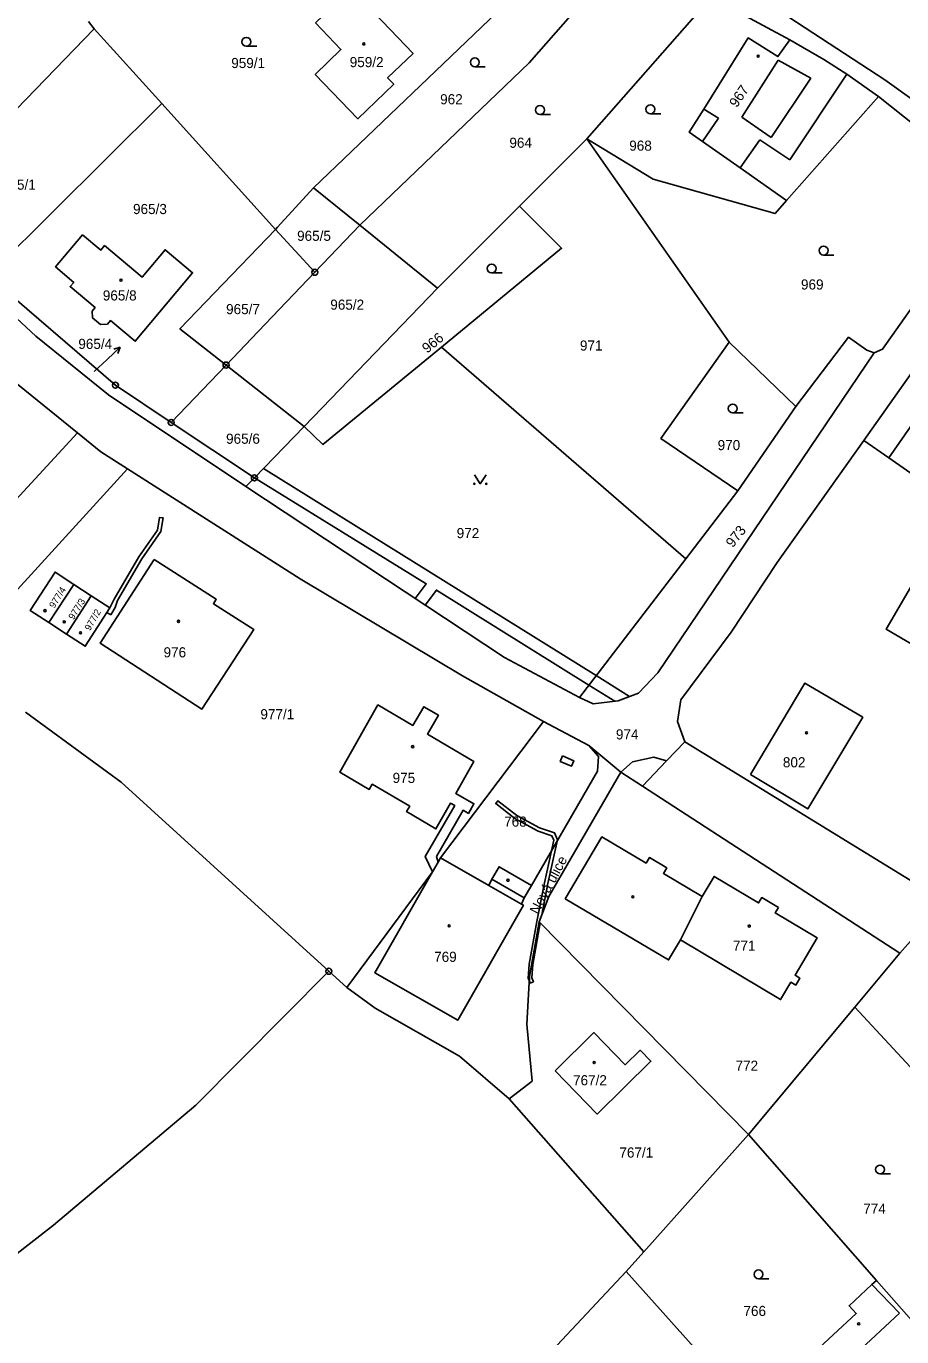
# Model space of a CAD drawing. Extents: x -504988 to -494607, y -1123820 to -1114018.
# Drawn here: x -497545.8 to -497398.6, y -1120433.9 to -1120213.7 of the extents above; entities that cross this region are included whole.
import ezdxf

# ---------------------------------------------------------------- set-up
doc = ezdxf.new("R2010")
doc.units = 0
for name, color, linetype in [('Hranice parcel', 7, 'Continuous'), ('Parcelní čísla', 7, 'Continuous'), ('Pop  PČ popisy', 7, 'Continuous'), ('Vnitřní kresba', 7, 'Continuous'), ('Věcná břemena k části', 7, 'Continuous'), ('Značky bodu BP', 7, 'Continuous'), ('Značky budov', 7, 'Continuous'), ('Značky kultur', 7, 'Continuous')]:
    doc.layers.add(name, color=color, linetype=linetype)

msp = doc.modelspace()

# ---------------------------------------------------------------- linework, layer by layer
at = {"layer": 'Hranice parcel'}
for p, q in [((-497465.37, -1120210.16), (-497497.45, -1120240.87)), ((-497430.82, -1120208.74), (-497417.41, -1120215.98)), ((-497534.33, -1120214.13), (-497535.29, -1120212.91)), ((-497563.92, -1120244.66), (-497534.33, -1120214.13)), ((-497522.97, -1120226.7), (-497534.33, -1120214.13)), ((-497417.92, -1120243), (-497402.47, -1120225.5)), ((-497552.14, -1120255.64), (-497522.97, -1120226.7)), ((-497503.85, -1120247.86), (-497522.97, -1120226.7)), ((-497462.83, -1120243.96), (-497451.51, -1120232.65)), ((-497451.51, -1120232.65), (-497427.61, -1120266.81)), ((-497497.45, -1120240.87), (-497489.7, -1120247.16)), ((-497476.62, -1120257.73), (-497462.83, -1120243.96)), ((-497514.12, -1120258.51), (-497503.85, -1120247.86)), ((-497503.85, -1120247.86), (-497497.25, -1120255.06)), ((-497489.7, -1120247.16), (-497497.25, -1120255.06)), ((-497489.7, -1120247.16), (-497476.62, -1120257.73)), ((-497499.05, -1120280.96), (-497476.62, -1120257.73)), ((-497475.95, -1120267.63), (-497434.88, -1120303.23)), ((-497427.61, -1120266.81), (-497416.37, -1120277.6)), ((-497521.38, -1120280.29), (-497512.16, -1120270.65)), ((-497512.16, -1120270.65), (-497499.05, -1120280.96)), ((-497400.74, -1120286.25), (-497393.19, -1120275.35)), ((-497426.11, -1120291.8), (-497416.37, -1120277.6)), ((-497507.4, -1120289.61), (-497521.38, -1120280.29)), ((-497499.05, -1120280.96), (-497507.4, -1120289.61)), ((-497537.13, -1120282.05), (-497566.22, -1120313.52)), ((-497400.74, -1120286.25), (-497404.97, -1120283.3)), ((-497557.94, -1120320.1), (-497528.73, -1120288.08)), ((-497508.81, -1120291.07), (-497507.4, -1120289.61)), ((-497434.88, -1120303.23), (-497426.11, -1120291.8)), ((-497452.76, -1120326.51), (-497434.88, -1120303.23)), ((-497537.76, -1120307.5), (-497541.94, -1120313.93)), ((-497537.76, -1120307.5), (-497534.82, -1120309.41)), ((-497534.82, -1120309.41), (-497538.99, -1120315.85)), ((-497538.99, -1120315.85), (-497541.94, -1120313.93)), ((-497458.82, -1120330.56), (-497476.11, -1120353.44)), ((-497445.81, -1120339.06), (-497442.15, -1120341.44)), ((-497442.15, -1120341.44), (-497398.87, -1120369.47)), ((-497476.11, -1120353.44), (-497476.53, -1120354.18)), ((-497477.45, -1120355.79), (-497491.87, -1120375.25)), ((-497476.53, -1120354.18), (-497477.45, -1120355.79)), ((-497459.54, -1120364.2), (-497424.35, -1120399.95)), ((-497398.87, -1120369.47), (-497395.34, -1120365.5)), ((-497406.47, -1120378.57), (-497398.87, -1120369.47)), ((-497491.87, -1120375.25), (-497494.88, -1120372.52)), ((-497424.35, -1120399.95), (-497406.47, -1120378.57)), ((-497381.93, -1120405.05), (-497406.47, -1120378.57)), ((-497441.91, -1120419.64), (-497464.56, -1120393.93)), ((-497424.35, -1120399.95), (-497441.91, -1120419.64)), ((-497402.82, -1120424.48), (-497424.35, -1120399.95)), ((-497441.91, -1120419.64), (-497444.89, -1120422.98)), ((-497444.89, -1120422.98), (-497466.63, -1120446.14)), ((-497422.13, -1120448.35), (-497444.89, -1120422.98)), ((-497383.69, -1120446.26), (-497402.82, -1120424.48))]:
    msp.add_line(p, q, dxfattribs=at)
for points in [[(-497434.54, -1120200.6), (-497429.66, -1120204.25), (-497401.43, -1120222.74), (-497391.53, -1120229.8), (-497382.81, -1120241.08)], [(-497489.7, -1120247.16), (-497461.23, -1120219.88), (-497446.5, -1120203.09)], [(-497497.14, -1120213.13), (-497491.11, -1120207.39), (-497480.72, -1120218.27), (-497485.01, -1120222.38), (-497483.97, -1120223.46), (-497490.02, -1120229.25), (-497497.16, -1120221.8), (-497492.84, -1120217.64), (-497497.14, -1120213.13)], [(-497451.51, -1120232.65), (-497431.41, -1120209.76), (-497430.82, -1120208.74)], [(-497417.41, -1120215.98), (-497419.39, -1120218.82), (-497424.36, -1120215.69), (-497431.84, -1120227.63), (-497434.29, -1120231.53), (-497432.08, -1120233.08), (-497425.76, -1120237.51), (-497417.92, -1120243)], [(-497417.41, -1120215.98), (-497411.68, -1120219.31), (-497407.82, -1120221.79), (-497402.47, -1120225.5)], [(-497402.47, -1120225.5), (-497393.75, -1120232.44), (-497385.34, -1120244.67)], [(-497451.51, -1120232.65), (-497440.34, -1120239.4), (-497419.86, -1120245.2), (-497417.92, -1120243)], [(-497371.73, -1120236.29), (-497376.09, -1120242.49), (-497404.97, -1120283.3)], [(-497497.45, -1120240.87), (-497503.53, -1120247.5), (-497503.85, -1120247.86)], [(-497475.95, -1120267.63), (-497455.76, -1120251.03), (-497462.83, -1120243.96)], [(-497385.34, -1120244.67), (-497401.79, -1120267.99), (-497403.21, -1120268.62)], [(-497508.81, -1120291.07), (-497531.94, -1120275.65), (-497544.12, -1120265.81), (-497565.3, -1120246.14)], [(-497532.1, -1120263.76), (-497533.27, -1120263.86), (-497534.6, -1120262.72), (-497534.67, -1120261.58), (-497534.18, -1120261), (-497538.39, -1120257.47), (-497537.77, -1120256.77), (-497540.83, -1120254.12), (-497536.29, -1120248.78), (-497533.21, -1120251.33), (-497532.58, -1120250.57), (-497526.25, -1120255.87), (-497522.42, -1120251.28), (-497517.8, -1120255.14), (-497527.43, -1120266.66), (-497531.6, -1120263.19), (-497532.1, -1120263.76)], [(-497552.14, -1120255.64), (-497530.76, -1120274.04), (-497521.38, -1120280.29)], [(-497497.25, -1120255.06), (-497506.77, -1120265.02), (-497512.16, -1120270.65)], [(-497512.16, -1120270.65), (-497519.93, -1120264.54), (-497514.12, -1120258.51)], [(-497499.05, -1120280.96), (-497495.88, -1120284.01), (-497475.95, -1120267.63)], [(-497427.61, -1120266.81), (-497439.05, -1120282.99), (-497426.11, -1120291.8)], [(-497416.37, -1120277.6), (-497407.52, -1120265.99), (-497404.44, -1120268.17), (-497403.21, -1120268.62)], [(-497552.38, -1120269.09), (-497547.17, -1120273.91), (-497537.13, -1120282.05)], [(-497403.21, -1120268.62), (-497439.58, -1120322.39), (-497442.82, -1120325.78), (-497446.22, -1120327.08), (-497450.46, -1120327.58), (-497452.76, -1120326.51)], [(-497537.13, -1120282.05), (-497533.19, -1120285.25), (-497528.73, -1120288.08)], [(-497404.97, -1120283.3), (-497419.52, -1120303.84), (-497427.22, -1120315.53), (-497435.73, -1120326.92)], [(-497354.64, -1120299.52), (-497365.47, -1120310.81), (-497400.74, -1120286.25)], [(-497528.73, -1120288.08), (-497499.69, -1120306.58), (-497472.4, -1120322.86), (-497458.82, -1120330.56)], [(-497452.76, -1120326.51), (-497465.33, -1120319.81), (-497508.81, -1120291.07)], [(-497382.34, -1120305.4), (-497391.45, -1120320.75), (-497401.18, -1120315.04), (-497392.22, -1120299.69), (-497382.34, -1120305.4)], [(-497524.25, -1120303.31), (-497533.3, -1120317.39), (-497516.22, -1120328.45), (-497507.47, -1120315.11), (-497514.3, -1120310.75), (-497513.82, -1120310.01), (-497524.25, -1120303.31)], [(-497541.94, -1120313.93), (-497545.07, -1120311.9), (-497540.91, -1120305.44), (-497537.76, -1120307.5)], [(-497534.82, -1120309.41), (-497531.69, -1120311.46), (-497535.83, -1120317.9), (-497538.99, -1120315.85)], [(-497423.98, -1120339.47), (-497414.86, -1120324.09), (-497405.12, -1120329.82), (-497414.33, -1120345.2), (-497423.98, -1120339.47)], [(-497435.73, -1120326.92), (-497436.28, -1120330.52), (-497435.05, -1120333.98)], [(-497494.88, -1120372.52), (-497529.79, -1120340.77), (-497545.88, -1120328.97)], [(-497476.53, -1120354.18), (-497476.76, -1120353.23), (-497472.32, -1120345.47), (-497471.43, -1120345.98), (-497470.5, -1120344.36), (-497473.52, -1120342.65), (-497470.48, -1120337.27), (-497478.32, -1120332.66), (-497476.47, -1120329.51), (-497478.93, -1120328.07), (-497480.78, -1120331.21), (-497486.64, -1120327.77), (-497493.01, -1120339.07), (-497488.1, -1120341.97), (-497487.58, -1120341.09), (-497481.28, -1120344.79), (-497481.81, -1120345.69), (-497476.89, -1120348.6), (-497474.44, -1120344.28), (-497473.72, -1120344.68), (-497478.68, -1120353.23), (-497477.45, -1120355.79)], [(-497458.82, -1120330.56), (-497451.18, -1120334.6), (-497445.81, -1120339.06)], [(-497435.05, -1120333.98), (-497438.1, -1120337.18), (-497442.15, -1120341.44)], [(-497459.54, -1120364.2), (-497457.9, -1120359.98), (-497445.81, -1120339.06)], [(-497419.29, -1120361.8), (-497422.1, -1120360.13), (-497422.64, -1120361.03), (-497430.12, -1120356.58), (-497432.12, -1120359.95), (-497438.64, -1120356.08), (-497438.07, -1120355.14), (-497440.99, -1120353.41), (-497441.55, -1120354.35), (-497448.97, -1120349.95), (-497455.13, -1120360.32), (-497437.78, -1120370.62), (-497435.78, -1120367.26), (-497418.93, -1120377.27), (-497417.2, -1120374.36), (-497416.38, -1120374.85), (-497415.69, -1120373.68), (-497416.51, -1120373.19), (-497412.78, -1120366.92), (-497419.83, -1120362.7), (-497419.29, -1120361.8)], [(-497476.11, -1120353.44), (-497467.97, -1120358.1), (-497467.47, -1120357.02), (-497466.26, -1120354.95), (-497460.84, -1120358.11), (-497462.05, -1120360.19), (-497462.52, -1120361.22), (-497462.16, -1120361.43), (-497473.21, -1120380.75), (-497487.17, -1120372.77), (-497477.45, -1120355.79)], [(-497464.56, -1120393.93), (-497460.69, -1120390.96), (-497461.57, -1120381.42), (-497461.13, -1120373.42), (-497459.54, -1120364.2)], [(-497646.41, -1120493.87), (-497618.78, -1120475.6), (-497541.15, -1120415.19), (-497517.26, -1120395.02), (-497494.88, -1120372.52)], [(-497491.87, -1120375.25), (-497487.07, -1120378.71), (-497472.93, -1120386.78), (-497464.56, -1120393.93)], [(-497456.86, -1120389.26), (-497450.35, -1120382.83), (-497445.06, -1120388.24), (-497442.55, -1120385.79), (-497440.74, -1120387.63), (-497449.79, -1120396.52), (-497456.86, -1120389.26)], [(-497402.82, -1120424.48), (-497403.57, -1120425.17), (-497407.41, -1120428.73), (-497406.21, -1120430.03), (-497413.98, -1120437.19), (-497410.66, -1120440.8), (-497406.8, -1120445.33), (-497400.09, -1120452.86), (-497391.43, -1120445.15), (-497387.36, -1120449.45)]]:
    msp.add_lwpolyline(points, dxfattribs=at)
at = {"layer": 'Pop  PČ popisy'}
for p, q in [((-497532.15, -1120269.69), (-497529.96, -1120267.64)), ((-497529.96, -1120267.64), (-497531.03, -1120267.96)), ((-497529.96, -1120267.64), (-497530.35, -1120268.69)), ((-497534.36, -1120271.73), (-497532.15, -1120269.69))]:
    msp.add_line(p, q, dxfattribs=at)
at = {"layer": 'Vnitřní kresba'}
for p, q in [((-497425.48, -1120228.99), (-497419.33, -1120219.41)), ((-497419.33, -1120219.41), (-497413.86, -1120222.46)), ((-497407.82, -1120221.79), (-497417.38, -1120236.14)), ((-497413.86, -1120222.46), (-497420.51, -1120232.42)), ((-497429.39, -1120229.17), (-497431.84, -1120227.63)), ((-497432.08, -1120233.08), (-497429.39, -1120229.17)), ((-497420.51, -1120232.42), (-497425.48, -1120228.99)), ((-497422.41, -1120232.79), (-497425.76, -1120237.51)), ((-497417.38, -1120236.14), (-497422.41, -1120232.79)), ((-497435.05, -1120333.98), (-497394.98, -1120358.54)), ((-497451.18, -1120334.6), (-497449.53, -1120336.43)), ((-497449.53, -1120336.43), (-497449.71, -1120338.89)), ((-497443.83, -1120337.34), (-497445.81, -1120339.06)), ((-497440.22, -1120336.53), (-497443.83, -1120337.34)), ((-497438.1, -1120337.18), (-497440.22, -1120336.53)), ((-497449.71, -1120338.89), (-497460.84, -1120358.11)), ((-497467.97, -1120358.1), (-497462.52, -1120361.22)), ((-497462.05, -1120360.19), (-497467.47, -1120357.02)), ((-497432.12, -1120359.95), (-497435.78, -1120367.26)), ((-497403.57, -1120425.17), (-497398.95, -1120429.99)), ((-497398.95, -1120429.99), (-497410.66, -1120440.8))]:
    msp.add_line(p, q, dxfattribs=at)
at = {"layer": 'Věcná břemena k části'}
for points in [[(-497449.94, -1120322.84), (-497505.86, -1120288.02), (-497507.4, -1120289.61), (-497478.51, -1120307.41), (-497480.35, -1120309.88), (-497478.68, -1120310.98), (-497476.81, -1120308.47), (-497451.17, -1120324.44), (-497446.81, -1120327.15), (-497446.22, -1120327.08), (-497444.31, -1120326.35)], [(-497531.52, -1120312.61), (-497530.82, -1120311.41), (-497530.43, -1120310.21), (-497526.3, -1120303.22), (-497523.11, -1120298.61), (-497522.75, -1120296.33), (-497523.35, -1120296.24), (-497523.69, -1120298.39), (-497526.8, -1120302.9), (-497530.99, -1120309.98), (-497531.69, -1120311.46), (-497532.18, -1120312.22)], [(-497455.58, -1120336.33), (-497455.98, -1120337.26), (-497454.1, -1120338.06), (-497453.71, -1120337.14)], [(-497459.7, -1120348.99), (-497457.38, -1120349.76), (-497457.07, -1120350.49), (-497458.63, -1120357.67), (-497459.91, -1120364.14), (-497461.19, -1120371.33), (-497461.36, -1120373.75), (-497461.17, -1120374.19), (-497461.13, -1120373.42), (-497459.54, -1120364.2), (-497459.08, -1120363.02), (-497458.05, -1120357.79), (-497456.45, -1120350.43), (-497456.94, -1120349.28), (-497459.46, -1120348.43), (-497463.27, -1120346.34), (-497466.45, -1120343.87), (-497466.82, -1120344.34), (-497463.61, -1120346.84)], [(-497459.54, -1120364.2), (-497461.13, -1120373.42), (-497461.17, -1120374.19), (-497461.04, -1120374.52), (-497460.49, -1120374.29), (-497460.76, -1120373.65), (-497460.59, -1120371.41), (-497459.35, -1120364.4)]]:
    msp.add_lwpolyline(points, close=True, dxfattribs=at)
at = {"layer": 'Značky bodu BP'}
for centre, radius in [((-497497.25, -1120255.06), 0.5), ((-497497.25, -1120255.06), 0.0303), ((-497512.16, -1120270.65), 0.5), ((-497512.16, -1120270.65), 0.0303), ((-497530.76, -1120274.04), 0.5), ((-497530.76, -1120274.04), 0.0303), ((-497521.38, -1120280.29), 0.5), ((-497521.38, -1120280.29), 0.0303), ((-497507.4, -1120289.61), 0.5), ((-497507.4, -1120289.61), 0.0303), ((-497494.88, -1120372.52), 0.5), ((-497494.88, -1120372.52), 0.0303)]:
    msp.add_circle(centre, radius, dxfattribs=at)
at = {"layer": 'Značky budov'}
for centre in [(-497488.99, -1120216.69), (-497422.71, -1120218.75), (-497529.83, -1120256.4), (-497542.6, -1120311.93), (-497539.36, -1120313.79), (-497520.16, -1120313.72), (-497536.64, -1120315.64), (-497414.57, -1120332.46), (-497480.79, -1120334.77), (-497464.77, -1120357.23), (-497443.79, -1120360.02), (-497474.67, -1120364.89), (-497424.2, -1120364.92), (-497450.28, -1120387.86), (-497405.81, -1120431.78)]:
    msp.add_circle(centre, 0.175, dxfattribs=at)
at = {"layer": 'Značky kultur'}
for p, q in [((-497508.76, -1120217.08), (-497507.01, -1120217.08)), ((-497470.34, -1120220.52), (-497468.59, -1120220.52)), ((-497440.82, -1120228.42), (-497439.07, -1120228.42)), ((-497459.38, -1120228.55), (-497457.63, -1120228.55)), ((-497411.71, -1120252.16), (-497409.96, -1120252.16)), ((-497467.52, -1120255.18), (-497465.77, -1120255.18)), ((-497426.98, -1120278.7), (-497425.23, -1120278.7)), ((-497402.21, -1120406.58), (-497400.46, -1120406.58)), ((-497422.65, -1120424.2), (-497420.9, -1120424.2))]:
    msp.add_line(p, q, dxfattribs=at)
msp.add_lwpolyline([(-497470.42, -1120289.1), (-497469.42, -1120290.6), (-497468.42, -1120289.1)], dxfattribs=at)
for centre, radius in [((-497508.76, -1120216.33), 0.75), ((-497470.34, -1120219.77), 0.75), ((-497459.38, -1120227.8), 0.75), ((-497440.82, -1120227.67), 0.75), ((-497411.71, -1120251.41), 0.75), ((-497467.52, -1120254.43), 0.75), ((-497426.98, -1120277.95), 0.75), ((-497470.42, -1120290.6), 0.1), ((-497468.42, -1120290.6), 0.1), ((-497402.21, -1120405.83), 0.75), ((-497422.65, -1120423.45), 0.75)]:
    msp.add_circle(centre, radius, dxfattribs=at)

# ---------------------------------------------------------------- texts
at = {"layer": 'Parcelní čísla'}
for s, p in [('959/1', (-497511.29, -1120220.74)), ('959/2', (-497491.37, -1120220.59)), ('962', (-497476.17, -1120226.83)), ('964', (-497464.53, -1120234.14)), ('968', (-497444.38, -1120234.63)), ('965/1', (-497549.84, -1120241.19)), ('965/3', (-497527.8, -1120245.28)), ('965/5', (-497500.22, -1120249.78)), ('969', (-497415.51, -1120257.96)), ('965/8', (-497532.88, -1120259.8)), ('965/7', (-497512.16, -1120262.1)), ('965/2', (-497494.64, -1120261.35)), ('965/4', (-497537, -1120267.94)), ('971', (-497452.67, -1120268.22)), ('965/6', (-497512.16, -1120283.88)), ('970', (-497429.52, -1120284.95)), ('972', (-497473.39, -1120299.74)), ('976', (-497522.67, -1120319.77)), ('977/1', (-497506.39, -1120330.17)), ('974', (-497446.62, -1120333.56)), ('802', (-497418.55, -1120338.25)), ('975', (-497484.16, -1120340.87)), ('768', (-497465.41, -1120348.22)), ('769', (-497477.18, -1120370.94)), ('771', (-497426.95, -1120369.08)), ('772', (-497426.51, -1120389.24)), ('767/2', (-497453.83, -1120391.68)), ('767/1', (-497446.04, -1120403.83)), ('774', (-497405.04, -1120413.27)), ('766', (-497425.18, -1120430.45))]:
    msp.add_text(s, height=1.7, dxfattribs=at).set_placement(p)
for s, height, rotation, p in [('967', 1.7, 56, (-497426.3, -1120227.5)), ('966', 1.7, 39, (-497478.36, -1120268.75)), ('973', 1.7, 52, (-497426.97, -1120301.44)), ('977/4', 1.139, 58, (-497541.03, -1120311.61)), ('977/3', 1.139, 58, (-497537.79, -1120313.55)), ('977/2', 1.139, 60, (-497535.03, -1120315.39))]:
    msp.add_text(s, height=height, rotation=rotation, dxfattribs=at).set_placement(p)
at = {"layer": 'Pop  PČ popisy'}
msp.add_text('Nová ulice', height=1.7, rotation=62, dxfattribs=at).set_placement((-497459.72, -1120363.08))

doc.saveas('drawing.dxf')
